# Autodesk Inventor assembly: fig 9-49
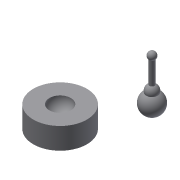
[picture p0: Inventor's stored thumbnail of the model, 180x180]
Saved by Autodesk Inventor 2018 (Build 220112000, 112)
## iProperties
Created: 2013-07
Part Number: fig 9-49
Document SubType Name: Assembly
Designer: CADCIM
Author: CADCIM
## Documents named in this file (3)
- E:\_Deepak\Inventor\Autodesk Inventor_2017_Project\Resources\Inventor_2018_Part\c09_Inv_2018\c09_inv_2018_prt\fig 9-49.iam
- E:\_Deepak\Inventor\Autodesk Inventor_2017_Project\Resources\Inventor_2018_Part\c09_Inv_2018\c09_inv_2018_prt\19.ipt
- E:\_Deepak\Inventor\Autodesk Inventor_2017_Project\Resources\Inventor_2018_Part\c09_Inv_2018\c09_inv_2018_prt\20.ipt
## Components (2 placed, 2 different names)
1. 19:1
2. 20:2
